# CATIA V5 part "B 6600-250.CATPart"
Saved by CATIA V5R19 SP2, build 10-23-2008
Part number: B 6600-250
Bounding box of the stored display mesh (mm): x -59.975 to 59.975, y -59.975 to 59.975, z 0 to 640
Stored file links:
  C:\Users\Bora\Desktop\3D Katı model\B serisi\B 6600\B 6600-250.CATPart
  C:\Program Files\Dassault Systemes\B19\intel_a\reffiles\standard\MetricThickPitch.txt
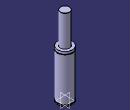
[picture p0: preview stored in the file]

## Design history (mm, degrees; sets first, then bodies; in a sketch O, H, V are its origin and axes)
Body1 (main body)
  Sketch1 on yz-plane, origin (0, 0, 0), H (0, 1, 0), V (0, 0, 1)
    point P3 (37.5, 639)
    point P5 (37.5, 639)
    point P10 (60, 362)
    point P11 (60, 367)
    point P13 (60, 367)
    point P14 (60, 362)
    line L1 (60, 0) -> (60, 8)
    line L2 (37.5, 639) -> (37.5, 387)
    arc A1 centre (36.5, 639) radius 1 from (37.5, 639) to (36.5, 640) ccw
    line L3 (56, 13) -> (56, 8)
    line L4 (60, 13) -> (60, 362)
    line L5 (60, 367) -> (60, 387)
    arc A2 centre (60, 364.5) radius 2.5 from (60, 367) to (60, 362) ccw
    line L6 (36.5, 640) -> (0, 640)
    point P15 (0, 640)
    line L7 (37.5, 387) -> (60, 387)
    line L8 (0, 0) -> (60, 0)
    line L9 (56, 13) -> (60, 13)
    line L10 (56, 8) -> (60, 8)
    coincidence: P15 V, P3 P5, P10 P14, P11 P13
    tangency: L6 A1
    horizontal: L7 H, L8 H, L9 H, L10 H
  Shaft1: profile Sketch1, axis Sketch1.V, angle 360
  Sketch2 on face of Shaft1 from Sketch1.L8, origin (0, 0, 0), H (1, 0, 0), V (0, -1, 0)
    point P1 (40, 0)
    distance P1 V = 40
  Hole1: placed by Sketch2, at (40, 0, 0) direction (0, 0, 1), diameter 8.376, depth 16, threaded "M10", thread diameter 10, thread depth 16, pitch 1.5
  CircPattern1: of Hole1, instances 4, angular step 90, axis from xy-plane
